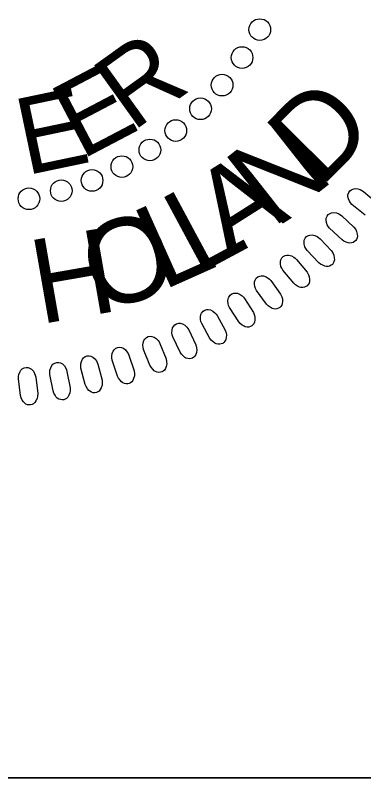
# Model space of a CAD drawing. Extents: x 1487909 to 1489267, y 497866 to 499814.
# Drawn here: x 1489045.319 to 1489047.457, y 498441.698 to 498446.38 of the extents above; entities that cross this region are included whole.
import ezdxf

# ---------------------------------------------------------------- set-up
doc = ezdxf.new("R2010")
doc.units = 0
for name, color, linetype in [('Old_Level_9', 7, 'Continuous'), ('Sheet Sticker Exception Certification CELL', 7, 'Continuous'), ('Sheet Typical CELL', 7, 'Continuous')]:
    doc.layers.add(name, color=color, linetype=linetype)

msp = doc.modelspace()

# ---------------------------------------------------------------- linework, layer by layer
at = {"layer": 'Old_Level_9'}
msp.add_lwpolyline([(1489047.4655, 498445.1518), (1489047.3848, 498445.2179), (1489047.3751, 498445.2283), (1489047.3686, 498445.2386), (1489047.3631, 498445.2527), (1489047.3601, 498445.2672), (1489047.3602, 498445.2777), (1489047.3647, 498445.291), (1489047.3714, 498445.3015), (1489047.3818, 498445.309), (1489047.3905, 498445.313), (1489047.4036, 498445.3159), (1489047.4207, 498445.3146), (1489047.4358, 498445.3094), (1489047.4457, 498445.3044), (1489047.4548, 498445.2985), (1489047.5332, 498445.2335)], dxfattribs=at)
for points in [[(1489047.3224, 498445.1482), (1489047.3966, 498445.0784), (1489047.4078, 498445.0637), (1489047.4133, 498445.0526), (1489047.4171, 498445.0362), (1489047.4182, 498445.0241), (1489047.4167, 498445.0127), (1489047.4132, 498445.0042), (1489047.4079, 498444.9963), (1489047.4004, 498444.9906), (1489047.3918, 498444.9851), (1489047.3823, 498444.9821), (1489047.3702, 498444.9815), (1489047.362, 498444.9824), (1489047.3491, 498444.9868), (1489047.3349, 498444.9934), (1489047.324, 498445.0011), (1489047.2476, 498445.0721), (1489047.2386, 498445.0831), (1489047.2327, 498445.0938), (1489047.2281, 498445.1082), (1489047.226, 498445.1229), (1489047.2268, 498445.1334), (1489047.232, 498445.1463), (1489047.2394, 498445.1564), (1489047.2503, 498445.1632), (1489047.2593, 498445.1667), (1489047.2725, 498445.1687), (1489047.2895, 498445.1663), (1489047.3042, 498445.1602), (1489047.3137, 498445.1546)], [(1489047.1886, 498445.0076), (1489047.2583, 498444.9333), (1489047.2685, 498444.9179), (1489047.2733, 498444.9065), (1489047.2761, 498444.8899), (1489047.2765, 498444.8777), (1489047.2742, 498444.8665), (1489047.2702, 498444.8581), (1489047.2644, 498444.8505), (1489047.2566, 498444.8454), (1489047.2476, 498444.8404), (1489047.2379, 498444.8381), (1489047.2259, 498444.8382), (1489047.2177, 498444.8396), (1489047.2052, 498444.8449), (1489047.1913, 498444.8523), (1489047.1809, 498444.8607), (1489047.1091, 498444.9363), (1489047.1008, 498444.9479), (1489047.0956, 498444.9589), (1489047.092, 498444.9736), (1489047.0908, 498444.9884), (1489047.0922, 498444.9988), (1489047.0983, 498445.0114), (1489047.1062, 498445.021), (1489047.1175, 498445.0271), (1489047.1267, 498445.03), (1489047.1401, 498445.0312), (1489047.1569, 498445.0278), (1489047.1712, 498445.0207), (1489047.1803, 498445.0146)], [(1489047.0448, 498444.8806), (1489047.1097, 498444.8021), (1489047.1189, 498444.7862), (1489047.123, 498444.7745), (1489047.1248, 498444.7577), (1489047.1244, 498444.7455), (1489047.1214, 498444.7345), (1489047.1168, 498444.7264), (1489047.1107, 498444.7192), (1489047.1025, 498444.7146), (1489047.0932, 498444.7102), (1489047.0834, 498444.7084), (1489047.0714, 498444.7093), (1489047.0634, 498444.7112), (1489047.0511, 498444.7172), (1489047.0378, 498444.7256), (1489047.0279, 498444.7346), (1489046.961, 498444.8145), (1489046.9535, 498444.8266), (1489046.949, 498444.8379), (1489046.9463, 498444.8528), (1489046.946, 498444.8677), (1489046.9481, 498444.878), (1489046.9549, 498444.8901), (1489046.9634, 498444.8993), (1489046.9751, 498444.9046), (1489046.9845, 498444.907), (1489046.9979, 498444.9073), (1489047.0144, 498444.9028), (1489047.0283, 498444.8948), (1489047.0371, 498444.8881)], [(1489046.8866, 498444.7507), (1489046.9464, 498444.6683), (1489046.9546, 498444.6517), (1489046.958, 498444.6398), (1489046.9587, 498444.623), (1489046.9574, 498444.6108), (1489046.9538, 498444.6), (1489046.9487, 498444.5922), (1489046.9422, 498444.5855), (1489046.9337, 498444.5813), (1489046.9242, 498444.5775), (1489046.9143, 498444.5763), (1489046.9023, 498444.578), (1489046.8944, 498444.5804), (1489046.8826, 498444.5872), (1489046.8698, 498444.5964), (1489046.8605, 498444.6059), (1489046.7988, 498444.69), (1489046.792, 498444.7025), (1489046.7883, 498444.7141), (1489046.7865, 498444.7291), (1489046.7872, 498444.744), (1489046.7898, 498444.7541), (1489046.7974, 498444.7658), (1489046.8066, 498444.7744), (1489046.8185, 498444.779), (1489046.828, 498444.7807), (1489046.8414, 498444.7803), (1489046.8576, 498444.7747), (1489046.871, 498444.7659), (1489046.8793, 498444.7587)], [(1489046.7252, 498444.6404), (1489046.7798, 498444.5544), (1489046.7869, 498444.5374), (1489046.7895, 498444.5253), (1489046.7891, 498444.5084), (1489046.7872, 498444.4964), (1489046.7829, 498444.4858), (1489046.7774, 498444.4784), (1489046.7703, 498444.472), (1489046.7616, 498444.4684), (1489046.7519, 498444.4652), (1489046.7419, 498444.4647), (1489046.7301, 498444.4671), (1489046.7224, 498444.47), (1489046.711, 498444.4775), (1489046.6988, 498444.4874), (1489046.6902, 498444.4976), (1489046.6338, 498444.5853), (1489046.6279, 498444.5982), (1489046.6248, 498444.61), (1489046.624, 498444.6252), (1489046.6256, 498444.64), (1489046.6289, 498444.6499), (1489046.6372, 498444.6611), (1489046.6469, 498444.6691), (1489046.6591, 498444.673), (1489046.6687, 498444.6741), (1489046.682, 498444.6728), (1489046.6979, 498444.6662), (1489046.7106, 498444.6566), (1489046.7184, 498444.6488)], [(1489046.5577, 498444.5362), (1489046.6067, 498444.4469), (1489046.6128, 498444.4295), (1489046.6145, 498444.4172), (1489046.6132, 498444.4004), (1489046.6105, 498444.3886), (1489046.6055, 498444.3783), (1489046.5995, 498444.3712), (1489046.5921, 498444.3653), (1489046.5832, 498444.3622), (1489046.5733, 498444.3597), (1489046.5633, 498444.3598), (1489046.5517, 498444.3629), (1489046.5441, 498444.3663), (1489046.5332, 498444.3745), (1489046.5217, 498444.3852), (1489046.5137, 498444.3959), (1489046.463, 498444.487), (1489046.4578, 498444.5002), (1489046.4555, 498444.5122), (1489046.4557, 498444.5273), (1489046.4582, 498444.542), (1489046.4621, 498444.5517), (1489046.4711, 498444.5623), (1489046.4812, 498444.5698), (1489046.4937, 498444.5728), (1489046.5033, 498444.5733), (1489046.5165, 498444.5712), (1489046.532, 498444.5636), (1489046.5441, 498444.5532), (1489046.5514, 498444.545)], [(1489046.3832, 498444.4479), (1489046.4265, 498444.3557), (1489046.4315, 498444.338), (1489046.4325, 498444.3257), (1489046.4301, 498444.3089), (1489046.4266, 498444.2973), (1489046.421, 498444.2873), (1489046.4146, 498444.2806), (1489046.4068, 498444.2752), (1489046.3978, 498444.2727), (1489046.3877, 498444.2708), (1489046.3777, 498444.2715), (1489046.3664, 498444.2754), (1489046.359, 498444.2792), (1489046.3487, 498444.288), (1489046.3379, 498444.2994), (1489046.3305, 498444.3106), (1489046.2856, 498444.4048), (1489046.2813, 498444.4183), (1489046.2798, 498444.4304), (1489046.2809, 498444.4455), (1489046.2843, 498444.4599), (1489046.2889, 498444.4694), (1489046.2985, 498444.4794), (1489046.3091, 498444.4862), (1489046.3217, 498444.4885), (1489046.3313, 498444.4884), (1489046.3443, 498444.4855), (1489046.3593, 498444.4769), (1489046.3708, 498444.4658), (1489046.3775, 498444.4571)], [(1489046.2066, 498444.3643), (1489046.244, 498444.2696), (1489046.2478, 498444.2516), (1489046.2481, 498444.2392), (1489046.2446, 498444.2227), (1489046.2405, 498444.2113), (1489046.2342, 498444.2017), (1489046.2274, 498444.1954), (1489046.2193, 498444.1904), (1489046.2101, 498444.1886), (1489046.1999, 498444.1872), (1489046.19, 498444.1886), (1489046.1789, 498444.1931), (1489046.1719, 498444.1975), (1489046.1621, 498444.207), (1489046.152, 498444.219), (1489046.1454, 498444.2306), (1489046.1065, 498444.3274), (1489046.103, 498444.3411), (1489046.1023, 498444.3533), (1489046.1043, 498444.3683), (1489046.1087, 498444.3825), (1489046.1138, 498444.3917), (1489046.124, 498444.4011), (1489046.135, 498444.4072), (1489046.1477, 498444.4087), (1489046.1574, 498444.408), (1489046.1702, 498444.4042), (1489046.1845, 498444.3948), (1489046.1953, 498444.383), (1489046.2015, 498444.3739)], [(1489046.0164, 498444.293), (1489046.0478, 498444.1962), (1489046.0504, 498444.1779), (1489046.0499, 498444.1656), (1489046.0454, 498444.1493), (1489046.0406, 498444.1381), (1489046.0337, 498444.129), (1489046.0265, 498444.1231), (1489046.0181, 498444.1187), (1489046.0088, 498444.1174), (1489045.9986, 498444.1167), (1489045.9888, 498444.1187), (1489045.978, 498444.1239), (1489045.9712, 498444.1287), (1489045.9621, 498444.1388), (1489045.9527, 498444.1514), (1489045.9469, 498444.1635), (1489045.9141, 498444.2624), (1489045.9115, 498444.2764), (1489045.9115, 498444.2886), (1489045.9145, 498444.3034), (1489045.9197, 498444.3173), (1489045.9254, 498444.3262), (1489045.9363, 498444.3349), (1489045.9475, 498444.3403), (1489045.9603, 498444.341), (1489045.9699, 498444.3397), (1489045.9825, 498444.3352), (1489045.9962, 498444.3248), (1489046.0062, 498444.3123), (1489046.0119, 498444.3029)], [(1489045.8261, 498444.2373), (1489045.8514, 498444.1386), (1489045.8529, 498444.1203), (1489045.8516, 498444.108), (1489045.8461, 498444.092), (1489045.8406, 498444.0812), (1489045.8332, 498444.0724), (1489045.8256, 498444.0671), (1489045.817, 498444.0632), (1489045.8076, 498444.0625), (1489045.7973, 498444.0624), (1489045.7877, 498444.065), (1489045.7772, 498444.0709), (1489045.7708, 498444.0761), (1489045.7623, 498444.0868), (1489045.7538, 498444.1), (1489045.7487, 498444.1123), (1489045.7222, 498444.2132), (1489045.7205, 498444.2273), (1489045.7212, 498444.2394), (1489045.7251, 498444.2541), (1489045.7312, 498444.2676), (1489045.7374, 498444.2761), (1489045.7488, 498444.2841), (1489045.7605, 498444.2888), (1489045.7733, 498444.2886), (1489045.7827, 498444.2868), (1489045.795, 498444.2815), (1489045.8081, 498444.2702), (1489045.8172, 498444.2572), (1489045.8223, 498444.2474)], [(1489045.4443, 498444.1586), (1489045.457, 498444.0576), (1489045.4562, 498444.0391), (1489045.4534, 498444.0271), (1489045.4459, 498444.0119), (1489045.439, 498444.0019), (1489045.4306, 498443.9941), (1489045.4224, 498443.9898), (1489045.4133, 498443.987), (1489045.404, 498443.9875), (1489045.3938, 498443.9887), (1489045.3845, 498443.9925), (1489045.3749, 498443.9997), (1489045.3691, 498444.0056), (1489045.362, 498444.0172), (1489045.3552, 498444.0314), (1489045.3517, 498444.0443), (1489045.3381, 498444.1477), (1489045.3382, 498444.1619), (1489045.3404, 498444.1739), (1489045.3462, 498444.1879), (1489045.3539, 498444.2005), (1489045.3611, 498444.2082), (1489045.3734, 498444.2147), (1489045.3856, 498444.2179), (1489045.3983, 498444.2161), (1489045.4074, 498444.2131), (1489045.4189, 498444.2063), (1489045.4304, 498444.1936), (1489045.4379, 498444.1794), (1489045.4417, 498444.1691)], [(1489045.6364, 498444.1927), (1489045.6554, 498444.0926), (1489045.6558, 498444.0742), (1489045.6538, 498444.062), (1489045.6473, 498444.0464), (1489045.641, 498444.0359), (1489045.6331, 498444.0277), (1489045.6252, 498444.0228), (1489045.6163, 498444.0195), (1489045.6069, 498444.0194), (1489045.5967, 498444.0199), (1489045.5872, 498444.0232), (1489045.5771, 498444.0297), (1489045.571, 498444.0352), (1489045.5632, 498444.0464), (1489045.5555, 498444.0601), (1489045.5512, 498444.0728), (1489045.5311, 498444.1751), (1489045.5303, 498444.1893), (1489045.5318, 498444.2014), (1489045.5367, 498444.2157), (1489045.5436, 498444.2289), (1489045.5503, 498444.2369), (1489045.5622, 498444.2442), (1489045.5741, 498444.2482), (1489045.5868, 498444.2472), (1489045.5962, 498444.2448), (1489045.6081, 498444.2387), (1489045.6204, 498444.2267), (1489045.6288, 498444.213), (1489045.6332, 498444.203)]]:
    msp.add_lwpolyline(points, close=True, dxfattribs=at)
for centre in [(1489046.8192, 498446.2922), (1489046.7101, 498446.1203), (1489046.5877, 498445.9517), (1489046.4555, 498445.8063), (1489046.3037, 498445.6721), (1489046.145, 498445.5531), (1489045.9732, 498445.4507), (1489045.79, 498445.3658), (1489045.6016, 498445.3031), (1489045.4033, 498445.2535)]:
    msp.add_circle(centre, 0.0665, dxfattribs=at)
at = {"layer": 'Sheet Sticker Exception Certification CELL'}
msp.add_line((1489029.9586, 498441.6976), (1489049.9623, 498441.6976), dxfattribs=at)
at = {"layer": 'Sheet Typical CELL'}
msp.add_lwpolyline([(1489039.9636, 498452.9476), (1489049.9636, 498452.9476), (1489049.9636, 498441.6976), (1489039.9636, 498441.6976)], close=True, dxfattribs=at)

# ---------------------------------------------------------------- texts
at = {"layer": 'Old_Level_9'}
for s, height, rotation, p in [('R', 0.4706, 35.6636, (1489046.0363, 498445.6608)), ('E', 0.4706, 27.7238, (1489045.7225, 498445.4896)), ('E', 0.4706, 11.8442, (1489045.3847, 498445.3964)), ('D', 0.5176, 45.281, (1489047.1927, 498445.3172)), ('N', 0.5176, 38.2091, (1489046.895, 498445.0673)), ('A', 0.5176, 32.3804, (1489046.628, 498444.8901)), ('L', 0.5176, 28.2433, (1489046.4282, 498444.7813)), ('L', 0.5176, 24.1061, (1489046.2211, 498444.6872)), ('O', 0.5176, 16.484, (1489045.824, 498444.5538)), ('H', 0.5176, 9.9012, (1489045.4694, 498444.4819))]:
    msp.add_text(s, height=height, rotation=rotation, dxfattribs=at).set_placement(p)

doc.saveas('drawing.dxf')
